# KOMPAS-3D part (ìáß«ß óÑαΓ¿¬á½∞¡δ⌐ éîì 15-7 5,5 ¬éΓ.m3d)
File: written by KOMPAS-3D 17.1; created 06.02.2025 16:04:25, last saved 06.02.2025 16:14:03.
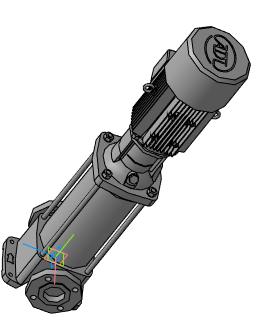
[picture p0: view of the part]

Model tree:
1. Операция без истории:1  (labels: Насос вертикальный ВМН 15-7 5,5 кВт)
